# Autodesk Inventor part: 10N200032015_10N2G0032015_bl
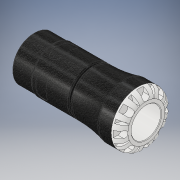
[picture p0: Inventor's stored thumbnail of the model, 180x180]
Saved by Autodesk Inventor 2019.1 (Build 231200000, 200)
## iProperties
Created: 2016-12
Part Number: 10N200032015_10N2G0032015_bl
Material: PVC-Piping
Description: PLASSON MALE ADAPTOR 32X1.1/2" SERIES 1
Document SubType Name: Modeling
Designer: KIM
Mass: 61.7504 g
Surface Area: 140.097 cm^2
Volume: 44.1074 cm^3
Density: 1.4 g/cm^3
Appearance: Black Cast
Author: KIM
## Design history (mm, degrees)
derived "10N20.ipt"
feature "Solid1::10N20.ipt" dims "ScaleForDerivedMember" = 10
tag "TaggingFeature1"
body "Solid1"
other parameters: "d0" = 122 [user parameter], "d1" = 23.1 [user parameter], "d2" = 32 [user parameter], "d4" = 58 [user parameter], "d6" = 55 [user parameter], "d8" = 49.3 [user parameter], "d13" = 7.2 [user parameter], "d14" = 7.2 [user parameter], "d15" = 0 [user parameter], "d17" = 360 deg [user parameter], "d19" = 8 deg [user parameter], "d20" = 0.64 [user parameter], "d21" = 0.64 [user parameter], "d22" = 8 deg [user parameter], "d24" = 0 [user parameter], "d26" = 360 deg [user parameter], "d32" = 0.925 [user parameter], "d33" = 5.8 [user parameter], "d34" = 47.803 [user parameter], "d35" = 2.66667 [user parameter], "d38" = 22 [user parameter], "d39" = 1.43409 [user parameter], "d42" = 11.2 [user parameter], "d43" = 7.36 [user parameter], "d45" = 14.112 [user parameter], "d46" = 0 [user parameter], "d59" = 360 deg [user parameter], "d61" = 9.52 [user parameter], "d62" = 0.64 [user parameter], "d64" = 0 [user parameter], "d65" = 0.58 [user parameter], "d69" = 2 [user parameter], "d70" = 1.83 [user parameter], "d71" = 3 [user parameter], "d73" = 1 [user parameter], "d_" = 32 [user parameter], "E_" = 58 [user parameter], "H_" = 122 [user parameter], "l_" = 55 [user parameter], "R_" = 47.803 [user parameter], "l_2" = 22 [user parameter], "d9" = 9 [user parameter], "d11" = 58 [user parameter]
